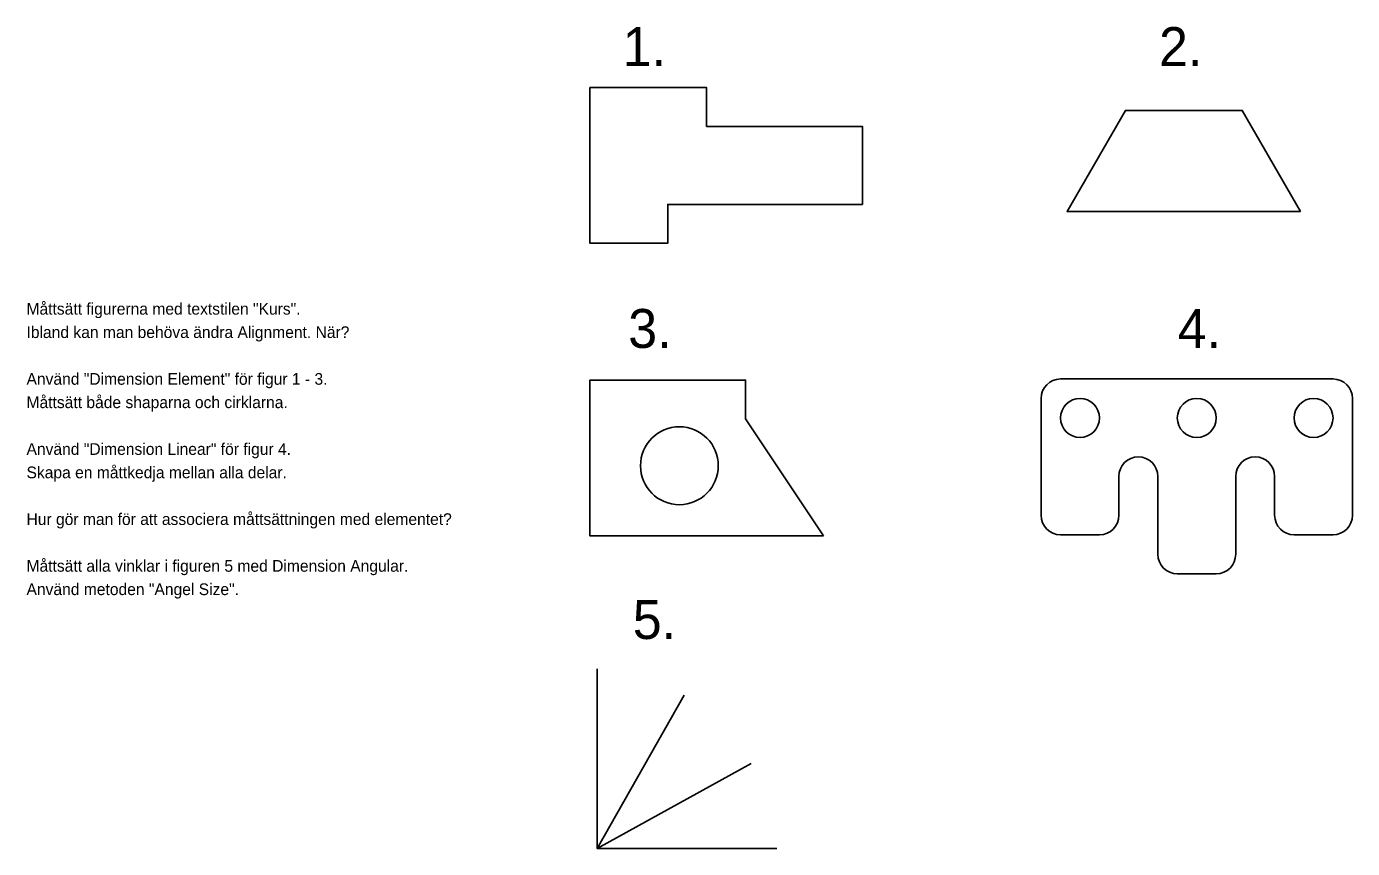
# Model space of a CAD drawing. Extents: x 6743 to 10150, y 2002 to 4112.
import ezdxf

# ---------------------------------------------------------------- set-up
doc = ezdxf.new("R2010")
doc.units = 0
doc.layers.add('Instruktioner', color=7, linetype='Continuous')
doc.layers.add('Lager 1', color=7, linetype='Continuous')

msp = doc.modelspace()

# ---------------------------------------------------------------- linework, layer by layer
at = {"layer": 'Lager 1'}
for p, q in [((9399.7, 3207.1), (10099.7, 3207.1)), ((9349.7, 2857.1), (9349.7, 3157.1)), ((10149.7, 3157.1), (10149.7, 2857.1)), ((9599.7, 3007.1), (9599.7, 3007.1)), ((9899.7, 3007.1), (9899.7, 3007.1)), ((9549.7, 2957.1), (9549.7, 2857.1)), ((9649.7, 2757.1), (9649.7, 2957.1)), ((9849.7, 2957.1), (9849.7, 2757.1)), ((9949.7, 2857.1), (9949.7, 2957.1)), ((9499.7, 2807.1), (9399.7, 2807.1)), ((10099.7, 2807.1), (9999.7, 2807.1)), ((9799.7, 2707.1), (9699.7, 2707.1)), ((8209.1, 2001.8), (8432.6, 2395.3)), ((8209.1, 2001.8), (8605.1, 2219.8))]:
    msp.add_line(p, q, dxfattribs=at)
for points in [[(8190.5, 3955.4), (8490.5, 3955.4), (8490.5, 3855.4), (8890.5, 3855.4), (8890.5, 3655.4), (8390.5, 3655.4), (8390.5, 3555.4), (8190.5, 3555.4)], [(10016.4, 3636.8), (9416.4, 3636.8), (9566.4, 3896.7), (9866.4, 3896.7)], [(8790.5, 2804.4), (8190.5, 2804.4), (8190.5, 3204.4), (8590.5, 3204.4), (8590.5, 3104.4)]]:
    msp.add_lwpolyline(points, close=True, dxfattribs=at)
msp.add_lwpolyline([(8209.1, 2463.2), (8209.1, 2001.8), (8670.4, 2001.8)], dxfattribs=at)
for centre, radius in [((9449.7, 3107.1), 50), ((9749.7, 3107.1), 50), ((10049.7, 3107.1), 50), ((8420.5, 2984.4), 100)]:
    msp.add_circle(centre, radius, dxfattribs=at)
for centre, start, end in [((9399.7, 3157.1), 90, 180), ((10099.7, 3157.1), 0, 90), ((9599.7, 2957.1), 90, 180), ((9599.7, 2957.1), 0, 90), ((9899.7, 2957.1), 90, 180), ((9899.7, 2957.1), 0, 90), ((9399.7, 2857.1), 180, 270), ((9499.7, 2857.1), 270, 0), ((9999.7, 2857.1), 180, 270), ((10099.7, 2857.1), 270, 0), ((9699.7, 2757.1), 180, 270), ((9799.7, 2757.1), 270, 0)]:
    msp.add_arc(centre, 50, start, end, dxfattribs=at)

# ---------------------------------------------------------------- texts
at = {"layer": 'Instruktioner'}
for s, height, p in [('1.', 100, (8274.8, 4010.4)), ('2.', 100, (9652.6, 4010.4)), ('Måttsätt figurerna med textstilen "Kurs".', 30, (6743.2, 3372.3)), ('3.', 100, (8289, 3286.8)), ('4.', 100, (9700.7, 3286.8)), ('Ibland kan man behöva ändra Alignment. När?', 30, (6743.2, 3312.3)), ('Använd "Dimension Element" för figur 1 - 3.', 30, (6743.2, 3192.3)), ('Måttsätt både shaparna och cirklarna.', 30, (6743.2, 3132.3)), ('Använd "Dimension Linear" för figur 4.', 30, (6743.2, 3012.3)), ('Skapa en måttkedja mellan alla delar.', 30, (6743.2, 2952.3)), ('Hur gör man för att associera måttsättningen med elementet?', 30, (6743.2, 2832.3)), ('Måttsätt alla vinklar i figuren 5 med Dimension Angular.', 30, (6743.2, 2712.3)), ('Använd metoden "Angel Size".', 30, (6743.2, 2652.3)), ('5.', 100, (8300.7, 2539.6))]:
    msp.add_text(s, height=height, dxfattribs=at).set_placement(p)

doc.saveas('drawing.dxf')
